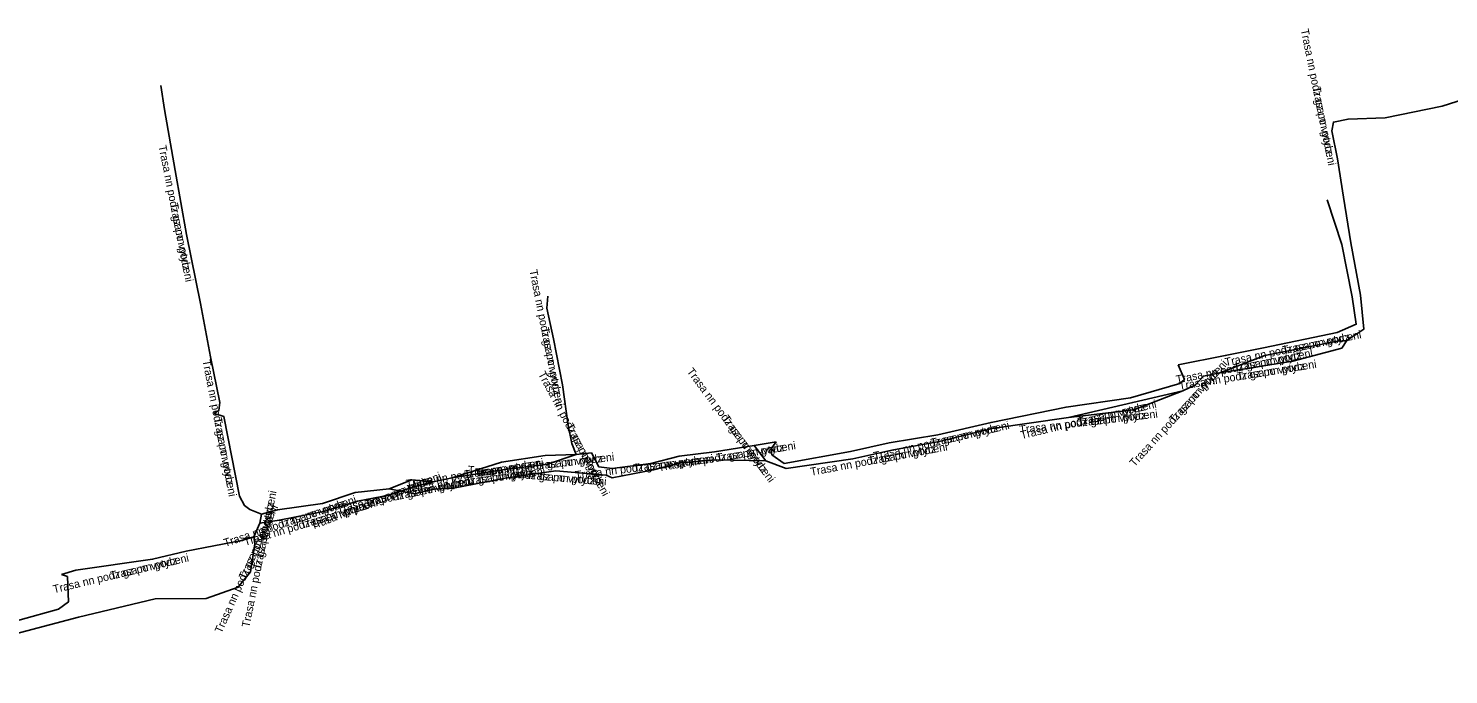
# Model space of a CAD drawing. Extents: x -876384 to -875659, y -1020218 to -1019588.
# Drawn here: x -875967.7 to -875879, y -1019860.8 to -1019820.4 of the extents above; entities that cross this region are included whole.
import ezdxf

# ---------------------------------------------------------------- set-up
doc = ezdxf.new("R2010")
doc.units = 0
doc.layers.add('Popiskový text - Ostatní atributy Trasy', color=7, linetype='Continuous')
doc.layers.add('Spojnice NN', color=7, linetype='Continuous')

msp = doc.modelspace()

# ---------------------------------------------------------------- linework, layer by layer
at = {"layer": 'Spojnice NN'}
for points in [[(-875959.47, -1019823.97), (-875959.23, -1019825.46), (-875958.57, -1019829.29), (-875957.85, -1019833.28), (-875956.99, -1019837.59), (-875956.35, -1019840.93), (-875955.77, -1019843.79), (-875955.84, -1019844.29), (-875956.15, -1019844.47)], [(-875959.47, -1019823.97), (-875959.23, -1019825.46), (-875958.57, -1019829.29), (-875957.85, -1019833.28), (-875956.99, -1019837.59), (-875956.35, -1019840.93), (-875955.77, -1019843.79), (-875955.84, -1019844.29), (-875956.15, -1019844.47)], [(-875885.35, -1019839.9), (-875884.28, -1019839.2), (-875884.49, -1019837.08), (-875885.1, -1019833.8), (-875885.54, -1019830.94), (-875885.92, -1019828.56), (-875886.28, -1019826.79), (-875886.18, -1019826.25), (-875885.26, -1019826.07), (-875882.95, -1019825.99), (-875879.38, -1019825.25), (-875875.66, -1019824.08), (-875873.75, -1019823.54)], [(-875885.35, -1019839.9), (-875884.28, -1019839.2), (-875884.49, -1019837.08), (-875885.1, -1019833.8), (-875885.54, -1019830.94), (-875885.92, -1019828.56), (-875886.28, -1019826.79), (-875886.18, -1019826.25), (-875885.26, -1019826.07), (-875882.95, -1019825.99), (-875879.38, -1019825.25), (-875875.66, -1019824.08), (-875873.75, -1019823.54)], [(-875886.56, -1019831.12), (-875885.65, -1019833.9), (-875885.01, -1019837.17), (-875884.75, -1019838.89), (-875885.95, -1019839.41), (-875890.55, -1019840.36), (-875892.94, -1019840.85), (-875895.88, -1019841.42)], [(-875886.56, -1019831.12), (-875885.65, -1019833.9), (-875885.01, -1019837.17), (-875884.75, -1019838.89), (-875885.95, -1019839.41), (-875890.55, -1019840.36), (-875892.94, -1019840.85), (-875895.88, -1019841.42)], [(-875935.28, -1019837.14), (-875935.33, -1019837.89), (-875934.92, -1019839.81), (-875934.35, -1019842.68), (-875934.01, -1019845.21), (-875933.77, -1019846.35), (-875933.51, -1019847.04)], [(-875935.28, -1019837.14), (-875935.33, -1019837.89), (-875934.92, -1019839.81), (-875934.35, -1019842.68), (-875934.01, -1019845.21), (-875933.77, -1019846.35), (-875933.51, -1019847.04)], [(-875893.27, -1019841.93), (-875890.46, -1019840.84), (-875885.94, -1019839.94), (-875885.35, -1019839.9)], [(-875893.27, -1019841.93), (-875888.71, -1019841.19), (-875885.66, -1019840.38), (-875885.35, -1019839.9)], [(-875893.27, -1019841.93), (-875890.46, -1019840.84), (-875885.94, -1019839.94), (-875885.35, -1019839.9)], [(-875893.27, -1019841.93), (-875888.71, -1019841.19), (-875885.66, -1019840.38), (-875885.35, -1019839.9)], [(-875895.88, -1019841.42), (-875895.49, -1019842.35), (-875895.78, -1019842.59), (-875898.86, -1019843.48), (-875902.89, -1019844.07), (-875907.57, -1019845.03), (-875910.9, -1019845.8), (-875913.94, -1019846.31), (-875916.37, -1019846.84), (-875920.5, -1019847.59), (-875921.27, -1019847.05), (-875921.34, -1019846.69), (-875921.01, -1019846.24)], [(-875895.88, -1019841.42), (-875895.49, -1019842.35), (-875895.78, -1019842.59), (-875898.86, -1019843.48), (-875902.89, -1019844.07), (-875907.57, -1019845.03), (-875910.9, -1019845.8), (-875913.94, -1019846.31), (-875916.37, -1019846.84), (-875920.5, -1019847.59), (-875921.27, -1019847.05), (-875921.34, -1019846.69), (-875921.01, -1019846.24)], [(-875895.59, -1019843.05), (-875894.8, -1019842.68), (-875894.3, -1019842.13), (-875893.27, -1019841.93)], [(-875895.59, -1019843.05), (-875894.8, -1019842.68), (-875894.3, -1019842.13), (-875893.27, -1019841.93)], [(-875902.74, -1019844.72), (-875898.65, -1019844.24), (-875895.59, -1019843.05)], [(-875902.74, -1019844.72), (-875898.72, -1019843.78), (-875895.59, -1019843.05)], [(-875902.74, -1019844.72), (-875898.65, -1019844.24), (-875895.59, -1019843.05)], [(-875902.74, -1019844.72), (-875898.72, -1019843.78), (-875895.59, -1019843.05)], [(-875956.15, -1019844.47), (-875955.77, -1019844.57), (-875955.52, -1019844.66), (-875954.55, -1019849.64), (-875954.23, -1019850.22), (-875953.9, -1019850.46), (-875953.17, -1019850.77)], [(-875956.15, -1019844.47), (-875955.77, -1019844.57), (-875955.52, -1019844.66), (-875954.55, -1019849.64), (-875954.23, -1019850.22), (-875953.9, -1019850.46), (-875953.17, -1019850.77)], [(-875921.66, -1019847.43), (-875920.38, -1019847.9), (-875916.22, -1019847.3), (-875913.77, -1019846.76), (-875910.82, -1019846.21), (-875907.5, -1019845.41), (-875902.74, -1019844.72)], [(-875921.66, -1019847.43), (-875920.38, -1019847.9), (-875916.22, -1019847.3), (-875913.77, -1019846.76), (-875910.82, -1019846.21), (-875907.5, -1019845.41), (-875902.74, -1019844.72)], [(-875921.01, -1019846.24), (-875922.38, -1019846.46)], [(-875921.01, -1019846.24), (-875922.38, -1019846.46)], [(-875933.51, -1019847.04), (-875935.45, -1019847.09), (-875938.17, -1019847.52), (-875941.26, -1019848.5)], [(-875933.51, -1019847.04), (-875935.3, -1019847.63), (-875938.1, -1019848), (-875941.26, -1019848.5)], [(-875933.51, -1019847.04), (-875935.45, -1019847.09), (-875938.17, -1019847.52), (-875941.26, -1019848.5)], [(-875933.51, -1019847.04), (-875935.3, -1019847.63), (-875938.1, -1019848), (-875941.26, -1019848.5)], [(-875932.55, -1019846.93), (-875933.51, -1019847.04)], [(-875932.55, -1019846.93), (-875933.51, -1019847.04)], [(-875931.26, -1019847.9), (-875932.09, -1019847.8), (-875932.55, -1019846.93)], [(-875931.26, -1019847.9), (-875932.09, -1019847.8), (-875932.55, -1019846.93)], [(-875922.38, -1019846.46), (-875924.85, -1019846.86), (-875927.07, -1019847.13), (-875928.84, -1019847.59), (-875931.26, -1019847.9)], [(-875922.38, -1019846.46), (-875924.85, -1019846.86), (-875927.07, -1019847.13), (-875928.84, -1019847.59), (-875931.26, -1019847.9)], [(-875922.38, -1019846.46), (-875921.66, -1019847.43)], [(-875922.38, -1019846.46), (-875921.66, -1019847.43)], [(-875945.2, -1019849.17), (-875943.6, -1019849.49), (-875942.39, -1019849.2), (-875941.17, -1019849.13), (-875937.95, -1019848.52), (-875934.77, -1019848.05), (-875931.62, -1019848.32), (-875931.26, -1019848.5), (-875928.67, -1019848), (-875926.99, -1019847.56), (-875924.76, -1019847.36), (-875921.66, -1019847.43)], [(-875945.2, -1019849.17), (-875943.6, -1019849.49), (-875942.39, -1019849.2), (-875941.17, -1019849.13), (-875937.95, -1019848.52), (-875934.77, -1019848.05), (-875931.62, -1019848.32), (-875931.26, -1019848.5), (-875928.67, -1019848), (-875926.99, -1019847.56), (-875924.76, -1019847.36), (-875921.66, -1019847.43)], [(-875942.45, -1019848.75), (-875943.66, -1019849.06), (-875945.22, -1019849.58), (-875947.17, -1019849.95), (-875949.29, -1019850.59), (-875952.06, -1019851.14), (-875953.28, -1019851.32)], [(-875942.45, -1019848.75), (-875943.66, -1019849.06), (-875945.22, -1019849.58), (-875947.17, -1019849.95), (-875949.29, -1019850.59), (-875952.06, -1019851.14), (-875953.28, -1019851.32)], [(-875942.45, -1019848.75), (-875943.77, -1019848.61), (-875945.2, -1019849.17)], [(-875942.45, -1019848.75), (-875943.77, -1019848.61), (-875945.2, -1019849.17)], [(-875941.26, -1019848.5), (-875942.45, -1019848.75)], [(-875941.26, -1019848.5), (-875942.45, -1019848.75)], [(-875953.17, -1019850.77), (-875952.17, -1019850.49), (-875949.35, -1019850.09), (-875947.32, -1019849.41), (-875945.2, -1019849.17)], [(-875953.17, -1019850.77), (-875952.17, -1019850.49), (-875949.35, -1019850.09), (-875947.32, -1019849.41), (-875945.2, -1019849.17)], [(-875953.66, -1019852.17), (-875953.28, -1019851.32)], [(-875953.66, -1019852.17), (-875953.28, -1019851.32)], [(-875953.28, -1019851.32), (-875953.17, -1019850.77)], [(-875953.28, -1019851.32), (-875953.17, -1019850.77)], [(-875994.05, -1019860.07), (-875992.96, -1019860.43), (-875991.88, -1019860.74), (-875990.79, -1019860.7), (-875989.9, -1019860.79), (-875985.75, -1019860.38), (-875981.22, -1019860.18), (-875980.21, -1019860.17), (-875978.83, -1019860.29), (-875976.96, -1019859.92), (-875973.42, -1019859.36), (-875970.38, -1019858.72), (-875964.6, -1019857.19), (-875959.81, -1019856.06), (-875956.63, -1019856.03), (-875954.62, -1019855.32), (-875953.85, -1019854.36), (-875953.58, -1019852.61), (-875953.66, -1019852.17)], [(-875994.05, -1019860.07), (-875992.96, -1019860.43), (-875991.88, -1019860.74), (-875990.79, -1019860.7), (-875989.9, -1019860.79), (-875985.75, -1019860.38), (-875981.22, -1019860.18), (-875980.21, -1019860.17), (-875978.83, -1019860.29), (-875976.96, -1019859.92), (-875973.42, -1019859.36), (-875970.38, -1019858.72), (-875964.6, -1019857.19), (-875959.81, -1019856.06), (-875956.63, -1019856.03), (-875954.62, -1019855.32), (-875953.85, -1019854.36), (-875953.58, -1019852.61), (-875953.66, -1019852.17)], [(-875953.66, -1019852.17), (-875954.42, -1019852.41), (-875957.87, -1019853.08), (-875959.98, -1019853.58), (-875964.78, -1019854.26), (-875965.67, -1019854.53)], [(-875953.66, -1019852.17), (-875954.42, -1019852.41), (-875957.87, -1019853.08), (-875959.98, -1019853.58), (-875964.78, -1019854.26), (-875965.67, -1019854.53)], [(-875990.74, -1019859), (-875991.13, -1019859.89), (-875990.97, -1019860.26), (-875989.87, -1019860.46), (-875985.77, -1019859.97), (-875981.16, -1019859.57), (-875980, -1019859.56), (-875977.41, -1019859.47), (-875973.58, -1019858.79), (-875970.66, -1019858.04), (-875965.85, -1019856.69), (-875965.24, -1019856.25), (-875965.3, -1019854.66), (-875965.67, -1019854.53)], [(-875990.74, -1019859), (-875991.13, -1019859.89), (-875990.97, -1019860.26), (-875989.87, -1019860.46), (-875985.77, -1019859.97), (-875981.16, -1019859.57), (-875980, -1019859.56), (-875977.41, -1019859.47), (-875973.58, -1019858.79), (-875970.66, -1019858.04), (-875965.85, -1019856.69), (-875965.24, -1019856.25), (-875965.3, -1019854.66), (-875965.67, -1019854.53)]]:
    msp.add_lwpolyline(points, dxfattribs=at)

# ---------------------------------------------------------------- texts
at = {"layer": 'Popiskový text - Ostatní atributy Trasy'}
for s, rotation, p in [('Trasa nn podz gz po vytyceni', 281.49656, (-875888.226, -1019820.482)), ('Trasa nn podz', 281.49656, (-875887.491, -1019824.093)), ('Trasa nn podz gz po vytyceni', 281.28437, (-875959.616, -1019827.749)), ('Trasa nn podz', 281.28437, (-875958.895, -1019831.363)), ('Trasa nn podz gz po vytyceni', 281.23313, (-875936.434, -1019835.523)), ('Trasa nn podz', 281.23313, (-875935.716, -1019839.137)), ('Trasa nn podz gz po vytyceni', 11.66877, (-875892.915, -1019841.512)), ('Trasa nn podz', 11.66877, (-875889.306, -1019840.766)), ('Trasa nn podz gz po vytyceni', 11.26117, (-875895.962, -1019842.598)), ('Trasa nn podz', 11.26117, (-875892.348, -1019841.879)), ('Trasa nn podz gz po vytyceni', 281.02202, (-875956.864, -1019841.159)), ('Trasa nn podz gz po vytyceni', 297.867, (-875935.893, -1019841.998)), ('Trasa nn podz gz po vytyceni', 306.58532, (-875926.614, -1019841.846)), ('Trasa nn podz gz po vytyceni', 47.72631, (-875898.606, -1019847.833)), ('Trasa nn podz', 47.72631, (-875896.127, -1019845.106)), ('Trasa nn podz gz po vytyceni', 9.21764, (-875895.79, -1019842.997)), ('Trasa nn podz', 9.21764, (-875892.153, -1019842.407)), ('Trasa nn podz gz po vytyceni', 6.69358, (-875905.775, -1019845.731)), ('Trasa nn podz gz po vytyceni', 13.16105, (-875905.67, -1019846.073)), ('Trasa nn podz', 13.16105, (-875902.082, -1019845.234)), ('Trasa nn podz', 6.69358, (-875902.115, -1019845.301)), ('Trasa nn podz', 281.02202, (-875956.159, -1019844.776)), ('Trasa nn podz', 297.867, (-875934.17, -1019845.255)), ('Trasa nn podz', 306.58532, (-875924.418, -1019844.805)), ('Trasa nn podz gz po vytyceni', 13.01975, (-875914.865, -1019847.384)), ('Trasa nn podz', 13.01975, (-875911.274, -1019846.554)), ('Trasa nn podz gz po vytyceni', 9.1229, (-875928.339, -1019848.075)), ('Trasa nn podz gz po vytyceni', 6.53663, (-875939.744, -1019848.408)), ('Trasa nn podz', 6.53663, (-875936.083, -1019847.989)), ('Trasa nn podz gz po vytyceni', 6.93435, (-875933.541, -1019848.572)), ('Trasa nn podz', 9.1229, (-875924.7, -1019847.491)), ('Trasa nn podz gz po vytyceni', 10.56101, (-875918.819, -1019848.363)), ('Trasa nn podz', 10.56101, (-875915.196, -1019847.688)), ('Trasa nn podz gz po vytyceni', 8.98344, (-875944.1, -1019849.116)), ('Trasa nn podz gz po vytyceni', 7.52762, (-875944.04, -1019849.441)), ('Trasa nn podz', 8.98344, (-875940.46, -1019848.54)), ('Trasa nn podz', 7.52762, (-875940.387, -1019848.958)), ('Trasa nn podz gz po vytyceni', 355.10091, (-875940.294, -1019848.229)), ('Trasa nn podz', 6.93435, (-875929.882, -1019848.127)), ('Trasa nn podz gz po vytyceni', 21.38573, (-875949.992, -1019851.744)), ('Trasa nn podz gz po vytyceni', 11.86439, (-875948.408, -1019850.665)), ('Trasa nn podz', 21.38573, (-875946.561, -1019850.401)), ('Trasa nn podz', 11.86439, (-875944.802, -1019849.908)), ('Trasa nn podz', 355.10091, (-875936.622, -1019848.543)), ('Trasa nn podz gz po vytyceni', 18.51958, (-875955.438, -1019852.815)), ('Trasa nn podz gz po vytyceni', 78.69007, (-875953.928, -1019857.872)), ('Trasa nn podz gz po vytyceni', 16.79837, (-875954.19, -1019852.748)), ('Trasa nn podz gz po vytyceni', 65.91255, (-875955.665, -1019858.248)), ('Trasa nn podz', 78.69007, (-875953.205, -1019854.259)), ('Trasa nn podz', 18.51958, (-875951.944, -1019851.645)), ('Trasa nn podz', 16.79837, (-875950.662, -1019851.683)), ('Trasa nn podz', 65.91255, (-875954.161, -1019854.884)), ('Trasa nn podz gz po vytyceni', 13.3313, (-875966.137, -1019855.707)), ('Trasa nn podz', 13.3313, (-875962.551, -1019854.857))]:
    msp.add_text(s, height=0.5, rotation=rotation, dxfattribs=at).set_placement(p)

doc.saveas('drawing.dxf')
